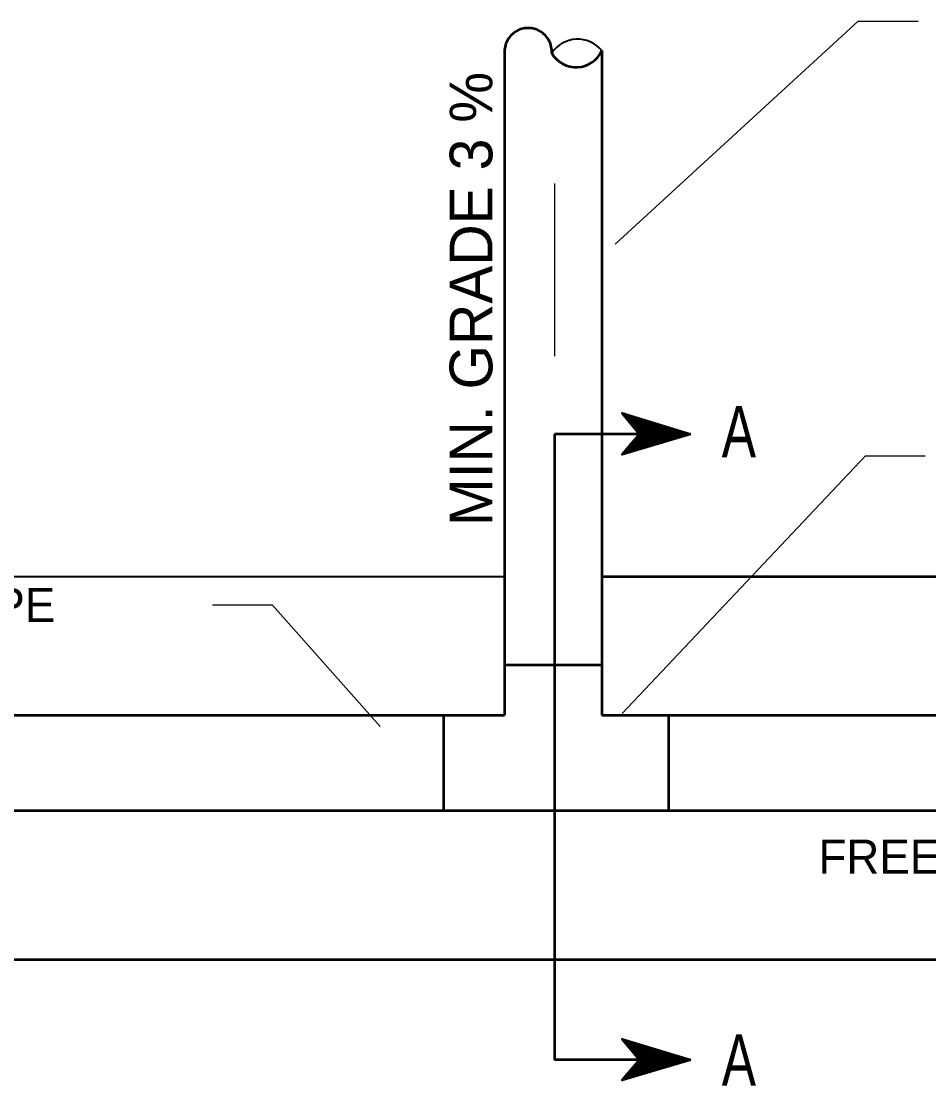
# Model space of a CAD drawing. Extents: x -48732 to -48696.6, y -117659.8 to -117637.8.
# Drawn here: x -48725.971 to -48723.897, y -117654.444 to -117652.011 of the extents above; entities that cross this region are included whole.
import ezdxf
from ezdxf.enums import TextEntityAlignment as Align

# ---------------------------------------------------------------- set-up
doc = ezdxf.new("R2010")
doc.units = 0
doc.header["$LTSCALE"] = 0.048
doc.layers.add('11', color=7, linetype='Continuous', lineweight=25)
doc.layers.add('24', color=7, linetype='Continuous', lineweight=40)

msp = doc.modelspace()

# ---------------------------------------------------------------- linework, layer by layer
at = {"layer": '11'}
msp.add_line((-48724.75183, -117652.38217), (-48724.75183, -117652.77617), dxfattribs=at)
at = {"layer": '11', "lineweight": 53}
for p, q in [((-48724.59642, -117652.90775), (-48724.59617, -117652.90733)), ((-48724.59583, -117652.9085), (-48724.59517, -117652.9075)), ((-48724.59517, -117652.90933), (-48724.59433, -117652.90783)), ((-48724.5945, -117652.91), (-48724.59342, -117652.90817)), ((-48724.59383, -117652.91083), (-48724.5925, -117652.90833)), ((-48724.59325, -117652.91167), (-48724.59158, -117652.90867)), ((-48724.59267, -117652.91233), (-48724.59067, -117652.909)), ((-48724.592, -117652.91317), (-48724.58975, -117652.90917)), ((-48724.59133, -117652.91392), (-48724.58883, -117652.9095)), ((-48724.59067, -117652.91467), (-48724.58792, -117652.90983)), ((-48724.59008, -117652.9155), (-48724.587, -117652.91008)), ((-48724.5895, -117652.91617), (-48724.58608, -117652.91033)), ((-48724.58883, -117652.917), (-48724.58517, -117652.91067)), ((-48724.58817, -117652.91783), (-48724.58433, -117652.91092)), ((-48724.5875, -117652.9185), (-48724.58333, -117652.91117)), ((-48724.58683, -117652.91933), (-48724.5825, -117652.9115)), ((-48724.58633, -117652.92008), (-48724.5815, -117652.91175)), ((-48724.58567, -117652.92083), (-48724.58067, -117652.912)), ((-48724.585, -117652.92167), (-48724.57967, -117652.91233)), ((-48724.58433, -117652.92233), (-48724.57883, -117652.91258)), ((-48724.58367, -117652.92317), (-48724.57783, -117652.91283)), ((-48724.58317, -117652.924), (-48724.577, -117652.91317)), ((-48724.5825, -117652.92467), (-48724.576, -117652.91342)), ((-48724.58183, -117652.9255), (-48724.57517, -117652.91367)), ((-48724.58117, -117652.92625), (-48724.57417, -117652.914)), ((-48724.5805, -117652.927), (-48724.57333, -117652.91425)), ((-48724.57992, -117652.92783), (-48724.57233, -117652.9145)), ((-48724.57933, -117652.9285), (-48724.5715, -117652.91483)), ((-48724.57867, -117652.92933), (-48724.5705, -117652.91508)), ((-48724.578, -117652.93017), (-48724.56967, -117652.91533)), ((-48724.57733, -117652.93083), (-48724.56867, -117652.91567)), ((-48724.57675, -117652.93167), (-48724.56783, -117652.916)), ((-48724.57617, -117652.93242), (-48724.56683, -117652.91617)), ((-48724.5755, -117652.93317), (-48724.566, -117652.9165)), ((-48724.57483, -117652.934), (-48724.565, -117652.91683)), ((-48724.57417, -117652.93467), (-48724.56417, -117652.917)), ((-48724.57358, -117652.9355), (-48724.56317, -117652.91733)), ((-48724.573, -117652.93625), (-48724.56233, -117652.91767)), ((-48724.57233, -117652.937), (-48724.56133, -117652.91783)), ((-48724.57167, -117652.93783), (-48724.5605, -117652.91817)), ((-48724.571, -117652.93858), (-48724.5595, -117652.9185)), ((-48724.57042, -117652.93933), (-48724.55867, -117652.91867)), ((-48724.56983, -117652.94017), (-48724.55767, -117652.919)), ((-48724.56917, -117652.94083), (-48724.55683, -117652.91933)), ((-48724.5685, -117652.94167), (-48724.55592, -117652.9195)), ((-48724.56783, -117652.94242), (-48724.555, -117652.91983)), ((-48724.56717, -117652.94317), (-48724.55408, -117652.92017)), ((-48724.56667, -117652.944), (-48724.55317, -117652.92033)), ((-48724.566, -117652.94475), (-48724.55225, -117652.92067)), ((-48724.56533, -117652.9455), (-48724.55133, -117652.921)), ((-48724.56467, -117652.94633), (-48724.55042, -117652.92117)), ((-48724.564, -117652.947), (-48724.5495, -117652.9215)), ((-48724.5635, -117652.94783), (-48724.54858, -117652.92183)), ((-48724.56283, -117652.94858), (-48724.54767, -117652.922)), ((-48724.56217, -117652.94933), (-48724.54683, -117652.92233)), ((-48724.5615, -117652.95017), (-48724.54583, -117652.92267)), ((-48724.56083, -117652.95083), (-48724.545, -117652.92292)), ((-48724.56025, -117652.95167), (-48724.544, -117652.92317)), ((-48724.55967, -117652.9525), (-48724.54317, -117652.9235)), ((-48724.58133, -117652.99617), (-48724.54033, -117652.92433)), ((-48724.58, -117652.99575), (-48724.5395, -117652.92458)), ((-48724.57867, -117652.99533), (-48724.5385, -117652.92483)), ((-48724.5775, -117652.995), (-48724.53767, -117652.92517)), ((-48724.57617, -117652.99467), (-48724.53667, -117652.92542)), ((-48724.57483, -117652.99417), (-48724.53583, -117652.92567)), ((-48724.5735, -117652.99383), (-48724.53483, -117652.926)), ((-48724.57233, -117652.9935), (-48724.534, -117652.92625)), ((-48724.571, -117652.99308), (-48724.533, -117652.9265)), ((-48724.56967, -117652.99267), (-48724.53217, -117652.92683)), ((-48724.56833, -117652.99233), (-48724.53117, -117652.92708)), ((-48724.56717, -117652.992), (-48724.53033, -117652.92733)), ((-48724.56583, -117652.9915), (-48724.52933, -117652.92767)), ((-48724.5645, -117652.99117), (-48724.5285, -117652.928)), ((-48724.56325, -117652.99083), (-48724.5275, -117652.92817)), ((-48724.562, -117652.99042), (-48724.52667, -117652.9285)), ((-48724.56067, -117652.99), (-48724.52567, -117652.92883)), ((-48724.55933, -117652.98967), (-48724.52483, -117652.929)), ((-48724.559, -117652.95317), (-48724.54217, -117652.92375)), ((-48724.55833, -117652.954), (-48724.54133, -117652.924)), ((-48724.55808, -117652.98933), (-48724.52383, -117652.92933)), ((-48724.55683, -117652.98883), (-48724.523, -117652.92967)), ((-48724.5555, -117652.9885), (-48724.522, -117652.92983)), ((-48724.55417, -117652.98817), (-48724.52117, -117652.93017)), ((-48724.55292, -117652.98775), (-48724.52017, -117652.9305)), ((-48724.55167, -117652.98733), (-48724.51933, -117652.93067)), ((-48724.55033, -117652.987), (-48724.51842, -117652.931)), ((-48724.549, -117652.98667), (-48724.5175, -117652.93133)), ((-48724.54775, -117652.98617), (-48724.51658, -117652.9315)), ((-48724.5465, -117652.98583), (-48724.51567, -117652.93183)), ((-48724.54517, -117652.9855), (-48724.51475, -117652.93217)), ((-48724.54383, -117652.98508), (-48724.51383, -117652.93233)), ((-48724.54258, -117652.98467), (-48724.51292, -117652.93267)), ((-48724.54133, -117652.98433), (-48724.512, -117652.933)), ((-48724.54, -117652.984), (-48724.51108, -117652.93317)), ((-48724.53867, -117652.98358), (-48724.51017, -117652.9335)), ((-48724.53742, -117652.98317), (-48724.50933, -117652.93383)), ((-48724.53617, -117652.98283), (-48724.50833, -117652.93408)), ((-48724.53483, -117652.9825), (-48724.5075, -117652.93433)), ((-48724.5335, -117652.982), (-48724.5065, -117652.93467)), ((-48724.53233, -117652.98167), (-48724.50567, -117652.93492)), ((-48724.531, -117652.98133), (-48724.50467, -117652.93517)), ((-48724.52967, -117652.98092), (-48724.50383, -117652.9355)), ((-48724.52833, -117652.9805), (-48724.50283, -117652.93575)), ((-48724.52717, -117652.98017), (-48724.502, -117652.936)), ((-48724.52583, -117652.97983), (-48724.501, -117652.93633)), ((-48724.5245, -117652.97933), (-48724.50017, -117652.93658)), ((-48724.52317, -117652.979), (-48724.49917, -117652.93683)), ((-48724.522, -117652.97867), (-48724.49833, -117652.93717)), ((-48724.52067, -117652.97825), (-48724.49733, -117652.93742)), ((-48724.51933, -117652.97783), (-48724.4965, -117652.93767)), ((-48724.518, -117652.9775), (-48724.4955, -117652.938)), ((-48724.51683, -117652.97717), (-48724.49467, -117652.93825)), ((-48724.5155, -117652.97667), (-48724.49367, -117652.9385)), ((-48724.51417, -117652.97633), (-48724.49283, -117652.93883)), ((-48724.51283, -117652.976), (-48724.49183, -117652.93908)), ((-48724.51167, -117652.97558), (-48724.491, -117652.93933)), ((-48724.51033, -117652.97517), (-48724.49, -117652.93967)), ((-48724.509, -117652.97483), (-48724.48917, -117652.94)), ((-48724.50775, -117652.9745), (-48724.48817, -117652.94017)), ((-48724.5065, -117652.974), (-48724.48733, -117652.9405)), ((-48724.50517, -117652.97367), (-48724.48633, -117652.94083)), ((-48724.50383, -117652.97333), (-48724.4855, -117652.941)), ((-48724.50258, -117652.97292), (-48724.4845, -117652.94133)), ((-48724.50133, -117652.9725), (-48724.48367, -117652.94167)), ((-48724.5, -117652.97217), (-48724.48275, -117652.94183)), ((-48724.49867, -117652.97183), (-48724.48183, -117652.94217)), ((-48724.49742, -117652.97133), (-48724.48092, -117652.9425)), ((-48724.49617, -117652.971), (-48724.48, -117652.94267)), ((-48724.49483, -117652.97067), (-48724.47908, -117652.943)), ((-48724.4935, -117652.97025), (-48724.47817, -117652.94333)), ((-48724.49225, -117652.96983), (-48724.47725, -117652.9435)), ((-48724.491, -117652.9695), (-48724.47633, -117652.94383)), ((-48724.48967, -117652.96917), (-48724.47542, -117652.94417)), ((-48724.48833, -117652.96867), (-48724.4745, -117652.94433)), ((-48724.48708, -117652.96833), (-48724.47358, -117652.94467)), ((-48724.48583, -117652.968), (-48724.47267, -117652.945)), ((-48724.4845, -117652.96758), (-48724.47183, -117652.94517)), ((-48724.48317, -117652.96717), (-48724.47083, -117652.9455)), ((-48724.48192, -117652.96683), (-48724.47, -117652.94583)), ((-48724.48067, -117652.9665), (-48724.469, -117652.946)), ((-48724.47933, -117652.966), (-48724.46817, -117652.94633)), ((-48724.478, -117652.96567), (-48724.46717, -117652.94667)), ((-48724.47683, -117652.96533), (-48724.46633, -117652.94692)), ((-48724.4755, -117652.96492), (-48724.46533, -117652.94717)), ((-48724.47417, -117652.9645), (-48724.4645, -117652.9475)), ((-48724.47283, -117652.96417), (-48724.4635, -117652.94775)), ((-48724.752, -117652.95467), (-48724.752, -117654.38467)), ((-48724.44083, -117652.95467), (-48724.752, -117652.95467)), ((-48724.5865, -117652.99767), (-48724.56983, -117652.9685)), ((-48724.58517, -117652.99733), (-48724.5665, -117652.9645)), ((-48724.58383, -117652.99683), (-48724.56317, -117652.96067)), ((-48724.58267, -117652.9965), (-48724.55983, -117652.95667)), ((-48724.47167, -117652.96383), (-48724.46267, -117652.948)), ((-48724.47033, -117652.96333), (-48724.46167, -117652.94833)), ((-48724.469, -117652.963), (-48724.46083, -117652.94858)), ((-48724.46767, -117652.96267), (-48724.45983, -117652.94883)), ((-48724.4665, -117652.96225), (-48724.459, -117652.94917)), ((-48724.46517, -117652.96183), (-48724.458, -117652.94942)), ((-48724.46383, -117652.9615), (-48724.45717, -117652.94967)), ((-48724.4625, -117652.96117), (-48724.45617, -117652.95)), ((-48724.46133, -117652.96067), (-48724.45533, -117652.95025)), ((-48724.46, -117652.96033), (-48724.45433, -117652.9505)), ((-48724.45867, -117652.96), (-48724.4535, -117652.95083)), ((-48724.45733, -117652.95958), (-48724.4525, -117652.95108)), ((-48724.45617, -117652.95917), (-48724.45167, -117652.95133)), ((-48724.45483, -117652.95883), (-48724.45067, -117652.95167)), ((-48724.4535, -117652.9585), (-48724.44983, -117652.95192)), ((-48724.45225, -117652.95808), (-48724.44883, -117652.95217)), ((-48724.451, -117652.95767), (-48724.448, -117652.9525)), ((-48724.44967, -117652.95733), (-48724.447, -117652.95283)), ((-48724.44833, -117652.957), (-48724.44617, -117652.953)), ((-48724.44708, -117652.9565), (-48724.44517, -117652.95333)), ((-48724.44583, -117652.95617), (-48724.44433, -117652.95367)), ((-48724.4445, -117652.95583), (-48724.44342, -117652.95383)), ((-48724.44317, -117652.95542), (-48724.4425, -117652.95417)), ((-48724.44192, -117652.955), (-48724.44158, -117652.9545)), ((-48724.5955, -117653.00033), (-48724.59317, -117652.99617)), ((-48724.59417, -117653), (-48724.58983, -117652.99217)), ((-48724.593, -117652.9995), (-48724.5865, -117652.98825)), ((-48724.59167, -117652.99917), (-48724.58317, -117652.98433)), ((-48724.59033, -117652.99883), (-48724.57983, -117652.98033)), ((-48724.589, -117652.99842), (-48724.5765, -117652.97642)), ((-48724.58783, -117652.998), (-48724.57317, -117652.9725)), ((-48724.59683, -117653.00067), (-48724.5965, -117653.00008)), ((-48724.59642, -117654.33783), (-48724.59617, -117654.33733)), ((-48724.59583, -117654.3385), (-48724.59517, -117654.33758)), ((-48724.59517, -117654.33933), (-48724.59433, -117654.33783)), ((-48724.5945, -117654.34008), (-48724.59342, -117654.33817)), ((-48724.59383, -117654.34083), (-48724.5925, -117654.33842)), ((-48724.59325, -117654.34167), (-48724.59158, -117654.33867)), ((-48724.59267, -117654.34233), (-48724.59067, -117654.339)), ((-48724.592, -117654.34317), (-48724.58975, -117654.33925)), ((-48724.59133, -117654.344), (-48724.58883, -117654.3395)), ((-48724.59067, -117654.34467), (-48724.58792, -117654.33983)), ((-48724.59008, -117654.3455), (-48724.587, -117654.34008)), ((-48724.5895, -117654.34625), (-48724.58608, -117654.34033)), ((-48724.58883, -117654.347), (-48724.58517, -117654.34067)), ((-48724.58817, -117654.34783), (-48724.58433, -117654.341)), ((-48724.5875, -117654.3485), (-48724.58333, -117654.34117)), ((-48724.58683, -117654.34933), (-48724.5825, -117654.3415)), ((-48724.58633, -117654.35017), (-48724.5815, -117654.34183)), ((-48724.58567, -117654.35083), (-48724.58067, -117654.342)), ((-48724.585, -117654.35167), (-48724.57967, -117654.34233)), ((-48724.58433, -117654.35242), (-48724.57883, -117654.34267)), ((-48724.58367, -117654.35317), (-48724.57783, -117654.34283)), ((-48724.58317, -117654.354), (-48724.577, -117654.34317)), ((-48724.5825, -117654.35467), (-48724.576, -117654.3435)), ((-48724.58183, -117654.3555), (-48724.57517, -117654.34367)), ((-48724.58133, -117654.42617), (-48724.54033, -117654.35433)), ((-48724.58117, -117654.35633), (-48724.57417, -117654.344)), ((-48724.5805, -117654.357), (-48724.57333, -117654.34433)), ((-48724.58, -117654.42583), (-48724.5395, -117654.35467)), ((-48724.57992, -117654.35783), (-48724.57233, -117654.3445)), ((-48724.57933, -117654.35858), (-48724.5715, -117654.34483)), ((-48724.57867, -117654.35933), (-48724.5705, -117654.34517)), ((-48724.57867, -117654.42533), (-48724.5385, -117654.35483)), ((-48724.578, -117654.36017), (-48724.56967, -117654.34533)), ((-48724.5775, -117654.425), (-48724.53767, -117654.35517)), ((-48724.57733, -117654.36083), (-48724.56867, -117654.34567)), ((-48724.57675, -117654.36167), (-48724.56783, -117654.346)), ((-48724.57617, -117654.3625), (-48724.56683, -117654.34617)), ((-48724.57617, -117654.42467), (-48724.53667, -117654.3555)), ((-48724.5755, -117654.36317), (-48724.566, -117654.3465)), ((-48724.57483, -117654.364), (-48724.565, -117654.34683)), ((-48724.57483, -117654.42425), (-48724.53583, -117654.35567)), ((-48724.57417, -117654.36475), (-48724.56417, -117654.347)), ((-48724.57358, -117654.3655), (-48724.56317, -117654.34733)), ((-48724.5735, -117654.42383), (-48724.53483, -117654.356)), ((-48724.573, -117654.36633), (-48724.56233, -117654.34767)), ((-48724.57233, -117654.367), (-48724.56133, -117654.34792)), ((-48724.57233, -117654.4235), (-48724.534, -117654.35633)), ((-48724.57167, -117654.36783), (-48724.5605, -117654.34817)), ((-48724.571, -117654.36867), (-48724.5595, -117654.3485)), ((-48724.571, -117654.42317), (-48724.533, -117654.3565)), ((-48724.57042, -117654.36933), (-48724.55867, -117654.34875)), ((-48724.56983, -117654.37017), (-48724.55767, -117654.349)), ((-48724.56967, -117654.42267), (-48724.53217, -117654.35683)), ((-48724.56917, -117654.37092), (-48724.55683, -117654.34933)), ((-48724.5685, -117654.37167), (-48724.55592, -117654.34958)), ((-48724.56833, -117654.42233), (-48724.53117, -117654.35717)), ((-48724.56783, -117654.3725), (-48724.555, -117654.34983)), ((-48724.56717, -117654.37317), (-48724.55408, -117654.35017)), ((-48724.56717, -117654.422), (-48724.53033, -117654.35733)), ((-48724.56667, -117654.374), (-48724.55317, -117654.35042)), ((-48724.566, -117654.37475), (-48724.55225, -117654.35067)), ((-48724.56583, -117654.42158), (-48724.52933, -117654.35767)), ((-48724.56533, -117654.3755), (-48724.55133, -117654.351)), ((-48724.56467, -117654.37633), (-48724.55042, -117654.35125)), ((-48724.5645, -117654.42117), (-48724.5285, -117654.358)), ((-48724.564, -117654.37708), (-48724.5495, -117654.3515)), ((-48724.5635, -117654.37783), (-48724.54858, -117654.35183)), ((-48724.56325, -117654.42083), (-48724.5275, -117654.35817)), ((-48724.56283, -117654.37867), (-48724.54767, -117654.35208)), ((-48724.56217, -117654.37933), (-48724.54683, -117654.35233)), ((-48724.562, -117654.4205), (-48724.52667, -117654.3585)), ((-48724.5615, -117654.38017), (-48724.54583, -117654.35267)), ((-48724.56083, -117654.38092), (-48724.545, -117654.35292)), ((-48724.56067, -117654.42), (-48724.52567, -117654.35883)), ((-48724.56025, -117654.38167), (-48724.544, -117654.35317)), ((-48724.55967, -117654.3825), (-48724.54317, -117654.3535)), ((-48724.559, -117654.38317), (-48724.54217, -117654.35383)), ((-48724.55833, -117654.384), (-48724.54133, -117654.354)), ((-48724.55933, -117654.41967), (-48724.52483, -117654.359)), ((-48724.55808, -117654.41933), (-48724.52383, -117654.35933)), ((-48724.55683, -117654.41892), (-48724.523, -117654.35967)), ((-48724.5555, -117654.4185), (-48724.522, -117654.35992)), ((-48724.55417, -117654.41817), (-48724.52117, -117654.36017)), ((-48724.55292, -117654.41783), (-48724.52017, -117654.3605)), ((-48724.55167, -117654.41733), (-48724.51933, -117654.36075)), ((-48724.55033, -117654.417), (-48724.51842, -117654.361)), ((-48724.549, -117654.41667), (-48724.5175, -117654.36133)), ((-48724.54775, -117654.41625), (-48724.51658, -117654.36158)), ((-48724.5465, -117654.41583), (-48724.51567, -117654.36183)), ((-48724.54517, -117654.4155), (-48724.51475, -117654.36217)), ((-48724.54383, -117654.41517), (-48724.51383, -117654.36242)), ((-48724.54258, -117654.41475), (-48724.51292, -117654.36267)), ((-48724.54133, -117654.41433), (-48724.512, -117654.363)), ((-48724.54, -117654.414), (-48724.51108, -117654.36325)), ((-48724.53867, -117654.41367), (-48724.51017, -117654.3635)), ((-48724.53742, -117654.41317), (-48724.50933, -117654.36383)), ((-48724.53617, -117654.41283), (-48724.50833, -117654.36408)), ((-48724.53483, -117654.4125), (-48724.5075, -117654.36433)), ((-48724.5335, -117654.41208), (-48724.5065, -117654.36467)), ((-48724.53233, -117654.41167), (-48724.50567, -117654.365)), ((-48724.531, -117654.41133), (-48724.50467, -117654.36517)), ((-48724.52967, -117654.411), (-48724.50383, -117654.3655)), ((-48724.52833, -117654.4105), (-48724.50283, -117654.36583)), ((-48724.52717, -117654.41017), (-48724.502, -117654.366)), ((-48724.52583, -117654.40983), (-48724.501, -117654.36633)), ((-48724.5245, -117654.40942), (-48724.50017, -117654.36667)), ((-48724.52317, -117654.409), (-48724.49917, -117654.36683)), ((-48724.522, -117654.40867), (-48724.49833, -117654.36717)), ((-48724.52067, -117654.40833), (-48724.49733, -117654.3675)), ((-48724.51933, -117654.40783), (-48724.4965, -117654.36767)), ((-48724.518, -117654.4075), (-48724.4955, -117654.368)), ((-48724.51683, -117654.40717), (-48724.49467, -117654.36833)), ((-48724.5155, -117654.40675), (-48724.49367, -117654.3685)), ((-48724.51417, -117654.40633), (-48724.49283, -117654.36883)), ((-48724.51283, -117654.406), (-48724.49183, -117654.36917)), ((-48724.51167, -117654.40567), (-48724.491, -117654.36933)), ((-48724.51033, -117654.40517), (-48724.49, -117654.36967)), ((-48724.509, -117654.40483), (-48724.48917, -117654.37)), ((-48724.50775, -117654.4045), (-48724.48817, -117654.37017)), ((-48724.5065, -117654.40408), (-48724.48733, -117654.3705)), ((-48724.50517, -117654.40367), (-48724.48633, -117654.37083)), ((-48724.50383, -117654.40333), (-48724.4855, -117654.371)), ((-48724.50258, -117654.403), (-48724.4845, -117654.37133)), ((-48724.50133, -117654.4025), (-48724.48367, -117654.37167)), ((-48724.5, -117654.40217), (-48724.48275, -117654.37192)), ((-48724.49867, -117654.40183), (-48724.48183, -117654.37217)), ((-48724.49742, -117654.40142), (-48724.48092, -117654.3725)), ((-48724.49617, -117654.401), (-48724.48, -117654.37275)), ((-48724.49483, -117654.40067), (-48724.47908, -117654.373)), ((-48724.4935, -117654.40033), (-48724.47817, -117654.37333)), ((-48724.49225, -117654.39983), (-48724.47725, -117654.37358)), ((-48724.491, -117654.3995), (-48724.47633, -117654.37383)), ((-48724.48967, -117654.39917), (-48724.47542, -117654.37417)), ((-48724.48833, -117654.39875), (-48724.4745, -117654.37442)), ((-48724.48708, -117654.39833), (-48724.47358, -117654.37467)), ((-48724.48583, -117654.398), (-48724.47267, -117654.375)), ((-48724.4845, -117654.39767), (-48724.47183, -117654.37525)), ((-48724.48317, -117654.39717), (-48724.47083, -117654.3755)), ((-48724.48192, -117654.39683), (-48724.47, -117654.37583)), ((-48724.48067, -117654.3965), (-48724.469, -117654.37608)), ((-48724.47933, -117654.39608), (-48724.46817, -117654.37633)), ((-48724.478, -117654.39567), (-48724.46717, -117654.37667)), ((-48724.47683, -117654.39533), (-48724.46633, -117654.37692)), ((-48724.4755, -117654.395), (-48724.46533, -117654.37717)), ((-48724.47417, -117654.3945), (-48724.4645, -117654.3775)), ((-48724.47283, -117654.39417), (-48724.4635, -117654.37783)), ((-48724.47167, -117654.39383), (-48724.46267, -117654.378)), ((-48724.47033, -117654.39342), (-48724.46167, -117654.37833)), ((-48724.469, -117654.393), (-48724.46083, -117654.37867)), ((-48724.46767, -117654.39267), (-48724.45983, -117654.37883)), ((-48724.4665, -117654.39233), (-48724.459, -117654.37917)), ((-48724.46517, -117654.39183), (-48724.458, -117654.3795)), ((-48724.46383, -117654.3915), (-48724.45717, -117654.37967)), ((-48724.4625, -117654.39117), (-48724.45617, -117654.38)), ((-48724.46133, -117654.39075), (-48724.45533, -117654.38033)), ((-48724.46, -117654.39033), (-48724.45433, -117654.3805)), ((-48724.45867, -117654.39), (-48724.4535, -117654.38083)), ((-48724.45733, -117654.38967), (-48724.4525, -117654.38117)), ((-48724.45617, -117654.38917), (-48724.45167, -117654.38133)), ((-48724.45483, -117654.38883), (-48724.45067, -117654.38167)), ((-48724.4535, -117654.3885), (-48724.44983, -117654.382)), ((-48724.45225, -117654.38808), (-48724.44883, -117654.38217)), ((-48724.451, -117654.38767), (-48724.448, -117654.3825)), ((-48724.44967, -117654.38733), (-48724.447, -117654.38283)), ((-48724.44833, -117654.387), (-48724.44617, -117654.383)), ((-48724.44083, -117654.38467), (-48724.752, -117654.38467)), ((-48724.589, -117654.4285), (-48724.5765, -117654.40642)), ((-48724.58783, -117654.428), (-48724.57317, -117654.4025)), ((-48724.5865, -117654.42767), (-48724.56983, -117654.3985)), ((-48724.58517, -117654.42733), (-48724.5665, -117654.39458)), ((-48724.58383, -117654.42692), (-48724.56317, -117654.39067)), ((-48724.58267, -117654.4265), (-48724.55983, -117654.38667)), ((-48724.44708, -117654.38658), (-48724.44517, -117654.38333)), ((-48724.44583, -117654.38617), (-48724.44433, -117654.38367)), ((-48724.4445, -117654.38583), (-48724.44342, -117654.38392)), ((-48724.44317, -117654.38542), (-48724.4425, -117654.38417)), ((-48724.44192, -117654.385), (-48724.44158, -117654.3845)), ((-48724.59683, -117654.43067), (-48724.5965, -117654.43017)), ((-48724.5955, -117654.43033), (-48724.59317, -117654.42617)), ((-48724.59417, -117654.43), (-48724.58983, -117654.42217)), ((-48724.593, -117654.42958), (-48724.5865, -117654.41833)), ((-48724.59167, -117654.42917), (-48724.58317, -117654.41433)), ((-48724.59033, -117654.42883), (-48724.57983, -117654.41033))]:
    msp.add_line(p, q, dxfattribs=at)
at = {"layer": '11'}
for points in [[(-48724.6135, -117652.5205), (-48724.05775, -117652.01117), (-48723.921, -117652.01117)], [(-48724.597, -117653.59333), (-48724.04133, -117653.0045), (-48723.9045, -117653.0045)], [(-48725.1505, -117653.623), (-48725.39692, -117653.34525), (-48725.53367, -117653.34525)]]:
    msp.add_lwpolyline(points, dxfattribs=at)
at = {"layer": '11', "lineweight": 53}
for points in [[(-48724.44083, -117652.95467), (-48724.597, -117653.00083), (-48724.558, -117652.95442), (-48724.597, -117652.907)], [(-48724.44083, -117654.38467), (-48724.597, -117654.43083), (-48724.558, -117654.3845), (-48724.597, -117654.337)]]:
    msp.add_lwpolyline(points, close=True, dxfattribs=at)
at = {"layer": '24', "lineweight": 53}
for p, q in [((-48724.86633, -117652.084), (-48724.86633, -117653.59708)), ((-48724.64383, -117652.07767), (-48724.64383, -117653.59708)), ((-48724.64383, -117653.27983), (-48721.92617, -117653.27983)), ((-48724.86633, -117653.482), (-48724.64383, -117653.482)), ((-48727.475, -117653.59708), (-48724.86633, -117653.59708)), ((-48725.00583, -117653.59708), (-48725.00583, -117653.81517)), ((-48724.64383, -117653.59708), (-48722.9295, -117653.59708)), ((-48724.49133, -117653.59708), (-48724.49133, -117653.81517)), ((-48727.46867, -117653.81517), (-48722.9295, -117653.81517)), ((-48727.68467, -117654.15533), (-48721.92617, -117654.15533))]:
    msp.add_line(p, q, dxfattribs=at)
at = {"layer": '24'}
msp.add_line((-48727.68467, -117653.27983), (-48724.86633, -117653.27983), dxfattribs=at)
at = {"layer": '24', "lineweight": 53}
for centre, radius, start, end in [((-48724.81232, -117652.08075), 0.05408, 356.5951, 183.4049), ((-48724.70266, -117652.05205), 0.06417, 209.82112, 336.53089)]:
    msp.add_arc(centre, radius, start, end, dxfattribs=at)
at = {"layer": '24'}
msp.add_arc((-48724.69868, -117652.12384), 0.07175, 40.10953, 146.24249, dxfattribs=at)

# ---------------------------------------------------------------- texts
at = {"layer": '11'}
msp.add_text('MIN. GRADE 3 %', height=0.09766, rotation=90, dxfattribs=at).set_placement((-48724.894, -117653.1645))
at = {"layer": '11', "width": 0.75}
for p in [(-48724.3305, -117653.00733), (-48724.3305, -117654.44375)]:
    msp.add_text('A', height=0.1172, dxfattribs=at).set_placement(p, align=Align.CENTER)
at = {"layer": '11'}
for s, p in [('6" PERFORATED PIPE', (-48726.9985, -117653.38433)), ('FREE DRAINING BASE TRENCH', (-48724.14867, -117653.9595))]:
    msp.add_text(s, height=0.07812, dxfattribs=at).set_placement(p)

doc.saveas('drawing.dxf')
